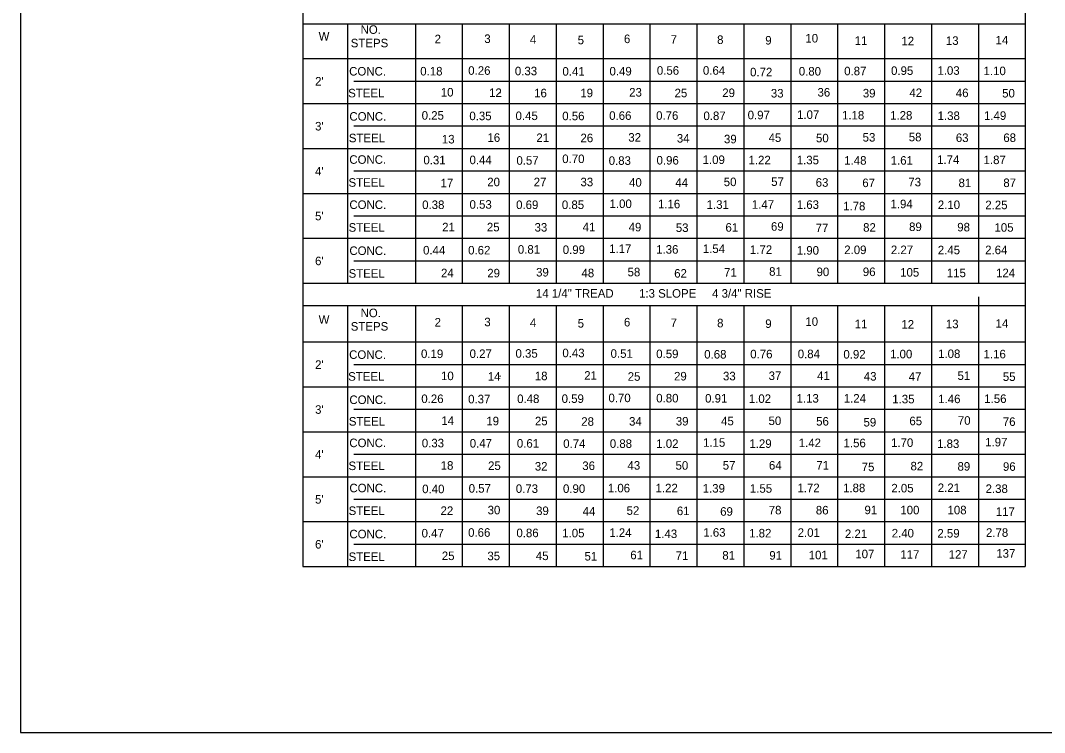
# Model space of a CAD drawing. Extents: x -439.5 to -408.2, y -792 to -771.6.
# Drawn here: x -439.46 to -422.81, y -791.98 to -780.41 of the extents above; entities that cross this region are included whole.
import ezdxf

# ---------------------------------------------------------------- set-up
doc = ezdxf.new("R2010")
doc.units = 0
doc.layers.add('Bridge-Named Boundary', color=7, linetype='Continuous')
doc.layers.add('Level 4', color=7, linetype='Continuous')

msp = doc.modelspace()

# ---------------------------------------------------------------- linework, layer by layer
at = {"layer": 'Bridge-Named Boundary'}
msp.add_lwpolyline([(-439.459, -791.984), (-408.209, -791.984), (-408.209, -771.609), (-439.459, -771.609)], close=True, dxfattribs=at)
at = {"layer": 'Level 4'}
for p, q in [((-434.87, -774.903), (-434.87, -789.286)), ((-423.125, -774.903), (-423.125, -789.286)), ((-434.87, -780.466), (-423.125, -780.466)), ((-434.143, -780.466), (-434.143, -784.679)), ((-433.04, -780.466), (-433.04, -784.679)), ((-432.278, -780.466), (-432.278, -784.679)), ((-431.515, -780.466), (-431.515, -784.679)), ((-430.753, -780.466), (-430.753, -784.679)), ((-429.989, -780.466), (-429.989, -784.679)), ((-429.227, -780.466), (-429.227, -784.679)), ((-428.464, -780.466), (-428.464, -784.679)), ((-427.702, -780.466), (-427.702, -784.679)), ((-426.938, -780.466), (-426.938, -784.679)), ((-426.176, -780.466), (-426.176, -784.679)), ((-425.412, -780.466), (-425.412, -784.679)), ((-424.65, -780.466), (-424.65, -784.679)), ((-423.887, -780.466), (-423.887, -784.679)), ((-434.87, -781.029), (-423.125, -781.029)), ((-434.038, -781.394), (-423.125, -781.394)), ((-434.87, -781.758), (-423.125, -781.758)), ((-434.038, -782.124), (-423.125, -782.124)), ((-434.87, -782.489), (-423.125, -782.489)), ((-434.038, -782.855), (-423.125, -782.855)), ((-434.87, -783.219), (-423.125, -783.219)), ((-434.038, -783.584), (-423.125, -783.584)), ((-434.87, -783.95), (-423.125, -783.95)), ((-434.038, -784.315), (-423.125, -784.315)), ((-434.87, -784.679), (-423.125, -784.679)), ((-434.87, -785.042), (-423.125, -785.042)), ((-434.143, -785.042), (-434.143, -789.286)), ((-433.04, -785.042), (-433.04, -789.286)), ((-432.278, -785.042), (-432.278, -789.286)), ((-431.515, -785.042), (-431.515, -789.286)), ((-430.753, -785.042), (-430.753, -789.286)), ((-429.989, -785.042), (-429.989, -789.286)), ((-429.227, -785.042), (-429.227, -789.286)), ((-428.464, -785.042), (-428.464, -789.286)), ((-427.702, -785.042), (-427.702, -789.286)), ((-426.938, -785.042), (-426.938, -789.286)), ((-426.176, -785.042), (-426.176, -789.286)), ((-425.412, -785.042), (-425.412, -789.286)), ((-424.65, -785.042), (-424.65, -789.286)), ((-423.887, -784.9), (-423.887, -789.286)), ((-434.87, -785.634), (-423.125, -785.634)), ((-434.038, -785.999), (-423.125, -785.999)), ((-434.87, -786.365), (-423.125, -786.365)), ((-434.038, -786.73), (-423.125, -786.73)), ((-434.87, -787.094), (-423.125, -787.094)), ((-434.038, -787.46), (-423.125, -787.46)), ((-434.87, -787.825), (-423.125, -787.825)), ((-434.038, -788.191), (-423.125, -788.191)), ((-434.87, -788.555), (-423.125, -788.555)), ((-434.038, -788.92), (-423.125, -788.92)), ((-434.87, -789.286), (-423.125, -789.286))]:
    msp.add_line(p, q, dxfattribs=at)
for centre in [(-431.616, -781.669), (-431.616, -786.274)]:
    msp.add_ellipse(centre, major_axis=(0.099, 0), ratio=0.96313, start_param=1.96543, end_param=2.160216, dxfattribs=at)

# ---------------------------------------------------------------- texts
for s, height, p in [('NO.', 0.1389, (-433.93, -780.626)), ('W', 0.139, (-434.612, -780.735)), ('STEPS', 0.1389, (-434.09, -780.845)), ('2', 0.139, (-432.727, -780.779)), ('3', 0.139, (-431.919, -780.775)), ('4', 0.139, (-431.178, -780.786)), ('5', 0.139, (-430.401, -780.796)), ('6', 0.139, (-429.649, -780.777)), ('7', 0.139, (-428.89, -780.787)), ('8', 0.139, (-428.135, -780.791)), ('9', 0.139, (-427.352, -780.801)), ('10', 0.1389, (-426.7, -780.767)), ('11', 0.1389, (-425.899, -780.806)), ('12', 0.1389, (-425.139, -780.812)), ('13', 0.1389, (-424.416, -780.806)), ('14', 0.1389, (-423.608, -780.798)), ('CONC.', 0.1389, (-434.116, -781.304)), ('0.18', 0.1389, (-432.96, -781.303)), ('0.26', 0.1389, (-432.18, -781.292)), ('0.33', 0.1389, (-431.422, -781.3)), ('0.41', 0.1389, (-430.649, -781.306)), ('0.49', 0.1389, (-429.884, -781.303)), ('0.56', 0.1389, (-429.114, -781.291)), ('0.64', 0.1389, (-428.365, -781.291)), ('0.72', 0.1389, (-427.599, -781.317)), ('0.80', 0.1389, (-426.807, -781.304)), ('0.87', 0.1389, (-426.069, -781.3)), ('0.95', 0.1389, (-425.307, -781.294)), ('1.03', 0.1389, (-424.553, -781.292)), ('1.10', 0.1389, (-423.803, -781.298)), ("2'", 0.1389, (-434.67, -781.467)), ('STEEL', 0.1389, (-434.132, -781.659)), ('10', 0.1389, (-432.626, -781.645)), ('12', 0.1389, (-431.842, -781.653)), ('16', 0.1389, (-431.109, -781.658)), ('19', 0.1389, (-430.358, -781.657)), ('23', 0.1389, (-429.564, -781.646)), ('25', 0.1389, (-428.826, -781.657)), ('29', 0.1389, (-428.051, -781.654)), ('33', 0.1389, (-427.261, -781.661)), ('36', 0.1389, (-426.503, -781.646)), ('39', 0.1389, (-425.766, -781.66)), ('42', 0.1389, (-425.009, -781.654)), ('46', 0.1389, (-424.254, -781.655)), ('50', 0.1389, (-423.501, -781.661)), ('0.25', 0.1389, (-432.937, -782.022)), ('0.45', 0.1389, (-431.411, -782.028)), ('0.66', 0.1389, (-429.889, -782.025)), ('0.76', 0.1389, (-429.126, -782.024)), ('0.87', 0.1389, (-428.357, -782.028)), ('0.97', 0.1389, (-427.638, -782.015)), ('1.07', 0.1389, (-426.835, -782.009)), ('1.18', 0.1389, (-426.104, -782.018)), ('1.28', 0.1389, (-425.322, -782.021)), ('1.38', 0.1389, (-424.55, -782.027)), ('1.49', 0.1389, (-423.796, -782.025)), ('CONC.', 0.1389, (-434.112, -782.038)), ('0.35', 0.1389, (-432.162, -782.03)), ('0.56', 0.1389, (-430.652, -782.031)), ("3'", 0.1389, (-434.67, -782.197)), ('STEEL', 0.1389, (-434.121, -782.389)), ('13', 0.1389, (-432.609, -782.408)), ('16', 0.1389, (-431.868, -782.382)), ('21', 0.1389, (-431.073, -782.385)), ('26', 0.1389, (-430.356, -782.388)), ('32', 0.1389, (-429.578, -782.379)), ('34', 0.1389, (-428.789, -782.394)), ('39', 0.1389, (-428.023, -782.406)), ('45', 0.1389, (-427.298, -782.384)), ('50', 0.1389, (-426.527, -782.39)), ('53', 0.1389, (-425.769, -782.378)), ('58', 0.1389, (-425.019, -782.373)), ('63', 0.1389, (-424.254, -782.385)), ('68', 0.1389, (-423.482, -782.384)), ('CONC.', 0.1389, (-434.113, -782.739)), ('0.31', 0.1389, (-432.909, -782.748)), ('0.44', 0.1389, (-432.159, -782.745)), ('0.57', 0.1389, (-431.397, -782.754)), ('0.70', 0.1389, (-430.652, -782.727)), ('0.83', 0.1389, (-429.897, -782.756)), ('0.96', 0.1389, (-429.119, -782.751)), ('1.09', 0.1389, (-428.37, -782.742)), ('1.22', 0.1389, (-427.624, -782.747)), ('1.35', 0.1389, (-426.84, -782.747)), ('1.48', 0.1389, (-426.068, -782.753)), ('1.61', 0.1389, (-425.313, -782.753)), ('1.74', 0.1389, (-424.559, -782.741)), ('1.87', 0.1389, (-423.803, -782.744)), ("4'", 0.1389, (-434.67, -782.928)), ('STEEL', 0.1389, (-434.126, -783.112)), ('17', 0.1389, (-432.63, -783.121)), ('20', 0.1389, (-431.871, -783.104)), ('27', 0.1389, (-431.116, -783.104)), ('33', 0.1389, (-430.356, -783.104)), ('40', 0.1389, (-429.566, -783.111)), ('44', 0.1389, (-428.814, -783.114)), ('50', 0.1389, (-428.027, -783.102)), ('57', 0.1389, (-427.256, -783.099)), ('63', 0.1389, (-426.532, -783.112)), ('67', 0.1389, (-425.774, -783.118)), ('73', 0.1389, (-425.026, -783.105)), ('81', 0.1389, (-424.21, -783.118)), ('87', 0.1389, (-423.482, -783.117)), ('CONC.', 0.1389, (-434.112, -783.473)), ('0.38', 0.1389, (-432.929, -783.474)), ('0.53', 0.1389, (-432.159, -783.469)), ('0.69', 0.1389, (-431.402, -783.474)), ('0.85', 0.1389, (-430.658, -783.474)), ('1.00', 0.1389, (-429.883, -783.458)), ('1.16', 0.1389, (-429.096, -783.462)), ('1.31', 0.1389, (-428.305, -783.471)), ('1.47', 0.1389, (-427.57, -783.47)), ('1.63', 0.1389, (-426.84, -783.472)), ('1.78', 0.1389, (-426.086, -783.496)), ('1.94', 0.1389, (-425.316, -783.461)), ('2.10', 0.1389, (-424.547, -783.475)), ('2.25', 0.1389, (-423.775, -783.477)), ("5'", 0.1389, (-434.67, -783.658)), ('STEEL', 0.1389, (-434.125, -783.843)), ('21', 0.1389, (-432.604, -783.837)), ('25', 0.1389, (-431.877, -783.837)), ('33', 0.1389, (-431.102, -783.841)), ('41', 0.1389, (-430.321, -783.837)), ('49', 0.1389, (-429.573, -783.837)), ('53', 0.1389, (-428.806, -783.847)), ('61', 0.1389, (-427.999, -783.843)), ('69', 0.1389, (-427.259, -783.827)), ('77', 0.1389, (-426.532, -783.85)), ('82', 0.1389, (-425.761, -783.843)), ('89', 0.1389, (-425.014, -783.832)), ('98', 0.1389, (-424.231, -783.838)), ('105', 0.1389, (-423.626, -783.843)), ('1.17', 0.1389, (-429.89, -784.189)), ('1.54', 0.1389, (-428.367, -784.189)), ('CONC.', 0.1389, (-434.112, -784.221)), ('0.44', 0.1389, (-432.915, -784.213)), ('0.62', 0.1389, (-432.182, -784.213)), ('0.81', 0.1389, (-431.374, -784.2)), ('0.99', 0.1389, (-430.644, -784.205)), ('1.36', 0.1389, (-429.125, -784.2)), ('1.72', 0.1389, (-427.601, -784.203)), ('1.90', 0.1389, (-426.84, -784.216)), ('2.09', 0.1389, (-426.068, -784.207)), ('2.27', 0.1389, (-425.31, -784.207)), ('2.45', 0.1389, (-424.547, -784.21)), ('2.64', 0.1389, (-423.777, -784.208)), ("6'", 0.1389, (-434.67, -784.388)), ('STEEL', 0.1389, (-434.125, -784.591)), ('24', 0.1389, (-432.623, -784.583)), ('29', 0.1389, (-431.871, -784.585)), ('39', 0.1389, (-431.077, -784.571)), ('48', 0.1389, (-430.339, -784.583)), ('58', 0.1389, (-429.59, -784.568)), ('62', 0.1389, (-428.832, -784.589)), ('71', 0.1389, (-428.022, -784.574)), ('81', 0.1389, (-427.289, -784.559)), ('90', 0.1389, (-426.518, -784.565)), ('96', 0.1389, (-425.766, -784.564)), ('105', 0.1389, (-425.159, -784.573)), ('115', 0.1389, (-424.401, -784.582)), ('124', 0.1389, (-423.6, -784.582)), ('14 1/4" TREAD        1:3 SLOPE     4 3/4" RISE', 0.13893, (-431.08, -784.915)), ('W', 0.139, (-434.612, -785.34)), ('NO.', 0.1389, (-433.93, -785.232)), ('STEPS', 0.1389, (-434.09, -785.451)), ('2', 0.139, (-432.727, -785.384)), ('3', 0.139, (-431.919, -785.38)), ('4', 0.139, (-431.178, -785.392)), ('5', 0.139, (-430.401, -785.402)), ('6', 0.139, (-429.649, -785.383)), ('7', 0.139, (-428.89, -785.393)), ('8', 0.139, (-428.135, -785.397)), ('9', 0.139, (-427.352, -785.407)), ('10', 0.1389, (-426.7, -785.373)), ('11', 0.1389, (-425.899, -785.412)), ('12', 0.1389, (-425.139, -785.418)), ('13', 0.1389, (-424.416, -785.412)), ('14', 0.1389, (-423.608, -785.404)), ('CONC.', 0.1389, (-434.116, -785.91)), ('0.19', 0.1389, (-432.948, -785.897)), ('0.27', 0.1389, (-432.158, -785.895)), ('0.35', 0.1389, (-431.412, -785.891)), ('0.43', 0.1389, (-430.65, -785.883)), ('0.51', 0.1389, (-429.866, -785.893)), ('0.59', 0.1389, (-429.124, -785.898)), ('0.68', 0.1389, (-428.344, -785.905)), ('0.76', 0.1389, (-427.596, -785.901)), ('0.84', 0.1389, (-426.824, -785.899)), ('0.92', 0.1389, (-426.082, -785.905)), ('1.00', 0.1389, (-425.323, -785.901)), ('1.08', 0.1389, (-424.542, -785.897)), ('1.16', 0.1389, (-423.803, -785.902)), ("2'", 0.1389, (-434.67, -786.073)), ('STEEL', 0.1389, (-434.132, -786.265)), ('10', 0.1389, (-432.623, -786.256)), ('14', 0.1389, (-431.862, -786.265)), ('18', 0.1389, (-431.098, -786.257)), ('21', 0.1389, (-430.295, -786.249)), ('25', 0.1389, (-429.588, -786.266)), ('29', 0.1389, (-428.835, -786.261)), ('33', 0.1389, (-428.039, -786.259)), ('37', 0.1389, (-427.297, -786.254)), ('41', 0.1389, (-426.51, -786.254)), ('43', 0.1389, (-425.75, -786.263)), ('47', 0.1389, (-425.02, -786.267)), ('51', 0.1389, (-424.227, -786.252)), ('55', 0.1389, (-423.49, -786.269)), ('CONC.', 0.1389, (-434.112, -786.644)), ('0.26', 0.1389, (-432.943, -786.628)), ('0.37', 0.1389, (-432.182, -786.633)), ('0.48', 0.1389, (-431.385, -786.628)), ('0.59', 0.1389, (-430.662, -786.626)), ('0.70', 0.1389, (-429.901, -786.614)), ('0.80', 0.1389, (-429.124, -786.618)), ('0.91', 0.1389, (-428.33, -786.621)), ('1.02', 0.1389, (-427.619, -786.626)), ('1.13', 0.1389, (-426.843, -786.621)), ('1.24', 0.1389, (-426.076, -786.621)), ('1.35', 0.1389, (-425.287, -786.633)), ('1.46', 0.1389, (-424.54, -786.63)), ('1.56', 0.1389, (-423.792, -786.627)), ("3'", 0.1389, (-434.67, -786.803)), ('STEEL', 0.1389, (-434.121, -786.995)), ('14', 0.1389, (-432.618, -786.985)), ('19', 0.1389, (-431.886, -786.99)), ('25', 0.1389, (-431.096, -786.99)), ('28', 0.1389, (-430.343, -786.998)), ('34', 0.1389, (-429.566, -786.995)), ('39', 0.1389, (-428.806, -786.993)), ('45', 0.1389, (-428.07, -786.99)), ('50', 0.1389, (-427.298, -786.986)), ('56', 0.1389, (-426.525, -786.994)), ('59', 0.1389, (-425.755, -787.009)), ('65', 0.1389, (-425.009, -786.989)), ('70', 0.1389, (-424.221, -786.981)), ('76', 0.1389, (-423.49, -787)), ('CONC.', 0.1389, (-434.113, -787.345)), ('0.33', 0.1389, (-432.935, -787.348)), ('0.47', 0.1389, (-432.156, -787.352)), ('0.61', 0.1389, (-431.39, -787.353)), ('1.15', 0.1389, (-428.363, -787.339)), ('1.42', 0.1389, (-426.808, -787.345)), ('1.56', 0.1389, (-426.079, -787.347)), ('1.70', 0.1389, (-425.307, -787.341)), ('1.97', 0.1389, (-423.777, -787.333)), ('0.74', 0.1389, (-430.636, -787.357)), ('0.88', 0.1389, (-429.879, -787.357)), ('1.02', 0.1389, (-429.124, -787.357)), ('1.29', 0.1389, (-427.61, -787.357)), ('1.83', 0.1389, (-424.559, -787.359)), ("4'", 0.1389, (-434.67, -787.533)), ('STEEL', 0.1389, (-434.126, -787.718)), ('18', 0.1389, (-432.628, -787.712)), ('25', 0.1389, (-431.858, -787.716)), ('32', 0.1389, (-431.098, -787.726)), ('36', 0.1389, (-430.326, -787.717)), ('43', 0.1389, (-429.591, -787.711)), ('50', 0.1389, (-428.81, -787.712)), ('57', 0.1389, (-428.043, -787.71)), ('64', 0.1389, (-427.292, -787.71)), ('71', 0.1389, (-426.522, -787.71)), ('75', 0.1389, (-425.784, -787.735)), ('82', 0.1389, (-424.991, -787.723)), ('89', 0.1389, (-424.227, -787.727)), ('96', 0.1389, (-423.488, -787.73)), ('CONC.', 0.1389, (-434.112, -788.079)), ('0.40', 0.1389, (-432.929, -788.094)), ('0.57', 0.1389, (-432.173, -788.085)), ('0.73', 0.1389, (-431.407, -788.089)), ('0.90', 0.1389, (-430.64, -788.089)), ('1.06', 0.1389, (-429.911, -788.08)), ('1.22', 0.1389, (-429.135, -788.079)), ('1.39', 0.1389, (-428.369, -788.084)), ('1.55', 0.1389, (-427.602, -788.086)), ('1.72', 0.1389, (-426.829, -788.077)), ('1.88', 0.1389, (-426.087, -788.077)), ('2.05', 0.1389, (-425.302, -788.081)), ('2.21', 0.1389, (-424.548, -788.075)), ('2.38', 0.1389, (-423.77, -788.09)), ("5'", 0.1389, (-434.67, -788.263)), ('STEEL', 0.1389, (-434.125, -788.448)), ('22', 0.1389, (-432.63, -788.447)), ('30', 0.1389, (-431.865, -788.437)), ('39', 0.1389, (-431.077, -788.449)), ('44', 0.1389, (-430.321, -788.458)), ('52', 0.1389, (-429.606, -788.445)), ('61', 0.1389, (-428.789, -788.45)), ('69', 0.1389, (-428.085, -788.46)), ('78', 0.1389, (-427.295, -788.438)), ('86', 0.1389, (-426.53, -788.439)), ('91', 0.1389, (-425.739, -788.435)), ('100', 0.1389, (-425.156, -788.437)), ('108', 0.1389, (-424.389, -788.437)), ('117', 0.1389, (-423.605, -788.463)), ('CONC.', 0.1389, (-434.112, -788.827)), ('0.47', 0.1389, (-432.938, -788.813)), ('0.66', 0.1389, (-432.182, -788.802)), ('0.86', 0.1389, (-431.397, -788.809)), ('1.05', 0.1389, (-430.652, -788.811)), ('1.24', 0.1389, (-429.887, -788.804)), ('1.43', 0.1389, (-429.145, -788.823)), ('1.63', 0.1389, (-428.359, -788.801)), ('1.82', 0.1389, (-427.614, -788.813)), ('2.01', 0.1389, (-426.825, -788.803)), ('2.21', 0.1389, (-426.057, -788.823)), ('2.40', 0.1389, (-425.296, -788.813)), ('2.59', 0.1389, (-424.554, -788.815)), ('2.78', 0.1389, (-423.764, -788.803)), ("6'", 0.1389, (-434.67, -788.994)), ('25', 0.1389, (-432.61, -789.181)), ('35', 0.1389, (-431.869, -789.183)), ('45', 0.1389, (-431.081, -789.181)), ('61', 0.1389, (-429.546, -789.168)), ('71', 0.1389, (-428.809, -789.18)), ('81', 0.1389, (-428.05, -789.174)), ('91', 0.1389, (-427.286, -789.174)), ('101', 0.1389, (-426.646, -789.168)), ('107', 0.1389, (-425.888, -789.151)), ('117', 0.1389, (-425.156, -789.159)), ('127', 0.1389, (-424.371, -789.159)), ('137', 0.1389, (-423.596, -789.142)), ('STEEL', 0.1389, (-434.125, -789.196)), ('51', 0.1389, (-430.29, -789.188))]:
    msp.add_text(s, height=height, dxfattribs=at).set_placement(p)

doc.saveas('drawing.dxf')
